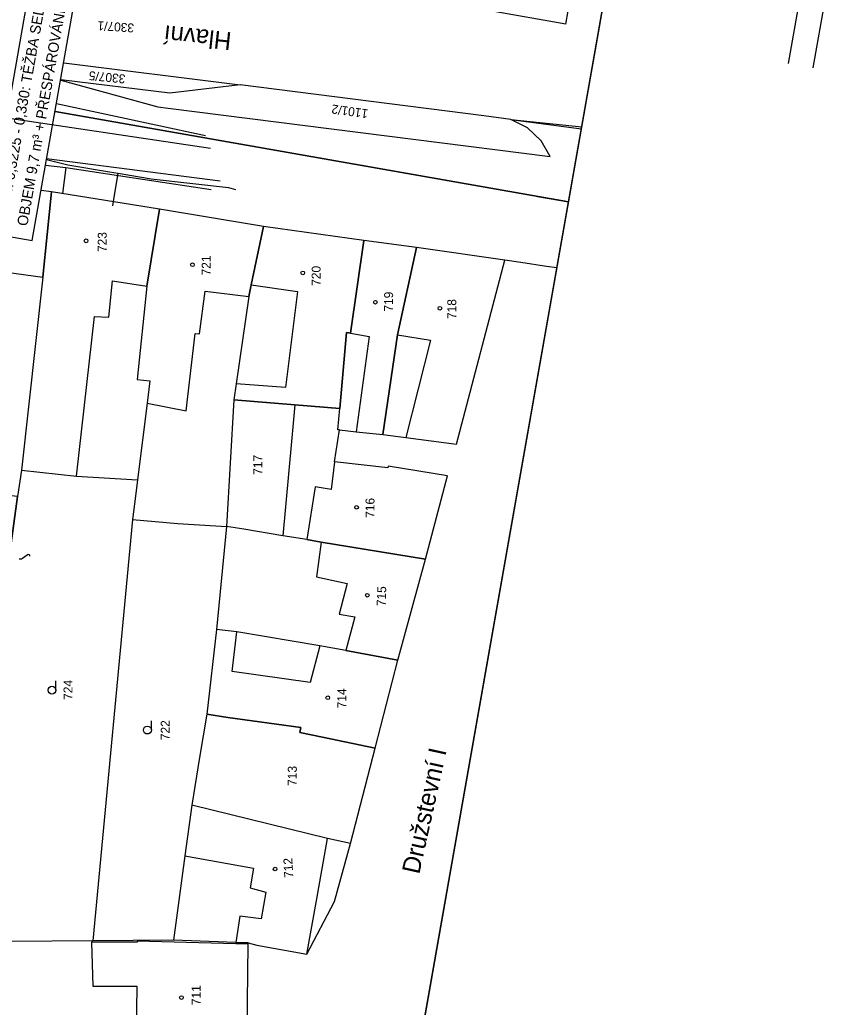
# Model space of a CAD drawing. Extents: x -534481 to -534256, y -1190577 to -1190138.
# Drawn here: x -534332 to -534255.5, y -1190343.4 to -1190249.6 of the extents above; entities that cross this region are included whole.
import ezdxf

# ---------------------------------------------------------------- set-up
doc = ezdxf.new("R2010")
doc.units = 0
for name, color, linetype in [('07_KANALIZACE', 7, 'Continuous'), ('14', 7, 'Continuous'), ('30', 7, 'Continuous'), ('31', 7, 'Continuous'), ('_N_text', 7, 'Continuous'), ('_rozpiska', 7, 'Continuous'), ('_rámeček', 7, 'Continuous'), ('_rámeček_mřížka', 7, 'Continuous'), ('_tenka', 7, 'Continuous'), ('Hranice parcel', 7, 'Continuous'), ('Parcelní čísla', 7, 'Continuous'), ('Polygon budovy', 7, 'Continuous'), ('Pop  PČ popisy', 7, 'Continuous'), ('Vrstva 1', 7, 'Continuous'), ('Značky budov', 7, 'Continuous'), ('Značky kultur', 7, 'Continuous')]:
    doc.layers.add(name, color=color, linetype=linetype)

msp = doc.modelspace()

# ---------------------------------------------------------------- linework, layer by layer
at = {"layer": '07_KANALIZACE'}
msp.add_line((-534328.555, -1190257.533), (-534314.388, -1190260.556), dxfattribs=at)
at = {"layer": '14'}
for points in [[(-534329.584, -1190263.371), (-534327.65, -1190263.6), (-534320.14, -1190264.75), (-534313.856, -1190265.686)], [(-534327.65, -1190263.6), (-534327.96, -1190266.08)]]:
    msp.add_lwpolyline(points, dxfattribs=at)
at = {"layer": '30'}
msp.add_line((-534258.995, -1190253.718), (-534257.831, -1190247.114), dxfattribs=at)
msp.add_lwpolyline([(-534332.097, -1190300.767), (-534331.981, -1190300.776), (-534331.867, -1190300.751), (-534331.755, -1190300.692), (-534331.313, -1190300.387), (-534331.218, -1190300.337), (-534331.152, -1190300.34), (-534331.115, -1190300.395), (-534331.109, -1190300.503)], dxfattribs=at)
at = {"layer": '31'}
msp.add_line((-534255.512, -1190247.523), (-534256.676, -1190254.127), dxfattribs=at)
at = {"layer": '_N_text'}
msp.add_lwpolyline([(-534329.865, -1190239.303), (-534335.236, -1190269.762), (-534330.848, -1190270.536), (-534325.477, -1190240.077)], close=True, dxfattribs=at)
at = {"layer": '_rozpiska'}
for q in [(-534265.393, -1190166.262), (-534313.394, -1190244.109)]:
    msp.add_line((-534280.153, -1190249.971), q, dxfattribs=at)
at = {"layer": '_rámeček'}
for p, q in [((-534279.901, -1190266.866), (-534261.668, -1190163.461)), ((-534298.134, -1190370.27), (-534279.901, -1190266.866))]:
    msp.add_line(p, q, dxfattribs=at)
for points in [[(-534407.912, -1190137.674), (-534480.845, -1190551.293), (-534334.601, -1190577.08), (-534261.668, -1190163.461)], [(-534328.654, -1190258.269), (-534279.901, -1190266.866)], [(-534279.901, -1190266.866), (-534328.654, -1190258.269)]]:
    msp.add_lwpolyline(points, dxfattribs=at)
at = {"layer": '_rámeček_mřížka'}
msp.add_line((-534282.856, -1190266.345), (-534279.901, -1190266.866), dxfattribs=at)
msp.add_lwpolyline([(-534480.845, -1190551.293), (-534334.601, -1190577.08), (-534261.668, -1190163.461)], dxfattribs=at)
at = {"layer": '_tenka'}
msp.add_lwpolyline([(-534367.462, -1190255.872), (-534340.907, -1190257.743), (-534313.909, -1190261.752)], dxfattribs=at)
at = {"layer": 'Hranice parcel'}
for p, q in [((-534327.842, -1190253.66), (-534311.1, -1190255.76)), ((-534318.76, -1190267.54), (-534329.03, -1190265.92)), ((-534308.86, -1190269.19), (-534318.76, -1190267.54)), ((-534299.34, -1190270.54), (-534308.86, -1190269.19)), ((-534294.34, -1190271.21), (-534299.34, -1190270.54)), ((-534285.95, -1190272.39), (-534294.34, -1190271.21)), ((-534311.69, -1190285.66), (-534312.39, -1190297.68)), ((-534305.91, -1190286.14), (-534311.69, -1190285.66)), ((-534305.91, -1190286.14), (-534306.23, -1190289.63)), ((-534301.62, -1190286.49), (-534305.91, -1190286.14)), ((-534306.23, -1190289.63), (-534307.05, -1190298.57)), ((-534321.31, -1190297.03), (-534325.09, -1190337.06)), ((-534312.39, -1190297.68), (-534313.35, -1190307.49)), ((-534296.1, -1190310.4), (-534293.5, -1190300.81)), ((-534313.35, -1190307.49), (-534314.25, -1190315.51)), ((-534298.26, -1190318.76), (-534296.1, -1190310.4)), ((-534300.61, -1190327.81), (-534298.26, -1190318.76)), ((-534325.09, -1190337.06), (-534332.83, -1190337.12)), ((-534317.41, -1190337), (-534325.09, -1190337.06))]:
    msp.add_line(p, q, dxfattribs=at)
for points in [[(-534328.129, -1190255.292), (-534318.9, -1190257.84), (-534317.93, -1190257.96), (-534281.65, -1190262.55), (-534282.51, -1190261.06), (-534283.8, -1190259.83), (-534285.39, -1190259.03)], [(-534311.1, -1190255.76), (-534317.76, -1190256.55), (-534328.125, -1190255.269)], [(-534285.39, -1190259.03), (-534287.93, -1190258.69), (-534311.1, -1190255.76)], [(-534285.39, -1190259.03), (-534278.677, -1190259.924)], [(-534285.39, -1190259.03), (-534278.645, -1190259.742)], [(-534329.03, -1190265.92), (-534330.011, -1190265.792)], [(-534329.03, -1190265.92), (-534329.83, -1190274.01), (-534331.85, -1190292.36)], [(-534318.76, -1190267.54), (-534319.95, -1190274.86), (-534320.89, -1190283.73), (-534319.66, -1190283.86), (-534319.92, -1190285.99), (-534320.83, -1190293.25)], [(-534308.86, -1190269.19), (-534310.04, -1190274.74), (-534310.28, -1190275.84), (-534311.47, -1190284.16), (-534311.69, -1190285.66)], [(-534299.34, -1190270.54), (-534300.62, -1190279.32), (-534300.98, -1190279.26), (-534301.62, -1190286.49)], [(-534294.34, -1190271.21), (-534296.16, -1190279.48), (-534297.54, -1190288.96)], [(-534297.54, -1190288.96), (-534295.37, -1190289.25), (-534290.54, -1190289.89), (-534285.95, -1190272.39)], [(-534281.008, -1190273.142), (-534282, -1190272.99), (-534284.44, -1190272.62), (-534285.95, -1190272.39)], [(-534301.66, -1190288.52), (-534301.8, -1190288.5), (-534301.62, -1190286.49)], [(-534293.5, -1190300.81), (-534291.39, -1190292.89), (-534297.04, -1190291.98), (-534297.07, -1190292.12), (-534302.14, -1190291.55), (-534301.66, -1190288.52)], [(-534301.66, -1190288.52), (-534300.07, -1190288.69), (-534297.54, -1190288.96)], [(-534331.85, -1190292.36), (-534332.25, -1190294.85), (-534333.12, -1190301.37), (-534333.95, -1190307.91)], [(-534331.85, -1190292.36), (-534326.64, -1190292.92), (-534320.83, -1190293.25)], [(-534320.83, -1190293.25), (-534320.97, -1190294.31), (-534321.31, -1190297.03)], [(-534321.31, -1190297.03), (-534317.01, -1190297.41), (-534312.39, -1190297.68)], [(-534307.05, -1190298.57), (-534310.73, -1190297.96), (-534312.39, -1190297.68)], [(-534293.5, -1190300.81), (-534303.4, -1190299.17), (-534304.76, -1190298.94), (-534307.05, -1190298.57)], [(-534296.1, -1190310.4), (-534301.05, -1190309.46), (-534303.52, -1190309.04), (-534311.4, -1190307.7), (-534313.35, -1190307.49)], [(-534314.25, -1190315.51), (-534314.94, -1190319.65), (-534315.69, -1190324.17)], [(-534298.26, -1190318.76), (-534303.28, -1190317.7), (-534305.42, -1190317.25), (-534305.33, -1190316.8), (-534312.25, -1190315.85), (-534314.25, -1190315.51)], [(-534315.69, -1190324.17), (-534316.34, -1190328.99), (-534317.41, -1190337)], [(-534300.61, -1190327.81), (-534302.8, -1190327.32), (-534315.69, -1190324.17)], [(-534310.32, -1190337.25), (-534309.51, -1190337.45), (-534304.75, -1190338.32), (-534302.13, -1190333.32), (-534300.61, -1190327.81)], [(-534310.32, -1190337.25), (-534311.5, -1190337.21), (-534317.41, -1190337)], [(-534315.73, -1190352.48), (-534310.81, -1190348.3), (-534310.45, -1190348.3), (-534310.32, -1190337.38), (-534310.32, -1190337.25)]]:
    msp.add_lwpolyline(points, dxfattribs=at)
at = {"layer": 'Polygon budovy'}
msp.add_lwpolyline([(-534334.434, -1190265.214), (-534341.12, -1190264.34), (-534341.18, -1190264.8), (-534342.09, -1190272.42), (-534339.77, -1190272.69), (-534343.2, -1190300.17), (-534333.12, -1190301.37), (-534332.25, -1190294.85), (-534337.72, -1190294.22), (-534334.94, -1190273.31), (-534329.83, -1190274.01), (-534329.03, -1190265.92), (-534330.011, -1190265.792)], dxfattribs=at)
for points in [[(-534329.03, -1190265.92), (-534329.83, -1190274.01), (-534331.85, -1190292.36), (-534326.64, -1190292.92), (-534324.94, -1190277.76), (-534323.57, -1190277.82), (-534323.23, -1190274.35), (-534319.95, -1190274.86), (-534318.76, -1190267.54)], [(-534319.92, -1190285.99), (-534316.22, -1190286.71), (-534315.36, -1190279.35), (-534314.97, -1190279.41), (-534314.43, -1190275.35), (-534310.28, -1190275.84), (-534310.04, -1190274.74), (-534308.86, -1190269.19), (-534318.76, -1190267.54), (-534319.95, -1190274.86), (-534320.89, -1190283.73), (-534319.66, -1190283.86)], [(-534311.69, -1190285.66), (-534305.91, -1190286.14), (-534301.62, -1190286.49), (-534300.98, -1190279.26), (-534300.62, -1190279.32), (-534299.34, -1190270.54), (-534308.86, -1190269.19), (-534310.04, -1190274.74), (-534305.65, -1190275.36), (-534306.77, -1190284.49), (-534311.47, -1190284.16)], [(-534300.07, -1190288.69), (-534297.54, -1190288.96), (-534296.16, -1190279.48), (-534294.34, -1190271.21), (-534299.34, -1190270.54), (-534300.62, -1190279.32), (-534298.85, -1190279.64)], [(-534295.37, -1190289.25), (-534290.54, -1190289.89), (-534285.95, -1190272.39), (-534294.34, -1190271.21), (-534296.16, -1190279.48), (-534293, -1190280.01)], [(-534302.14, -1190291.55), (-534302.44, -1190294.18), (-534303.96, -1190293.94), (-534304.76, -1190298.94), (-534303.4, -1190299.17), (-534293.5, -1190300.81), (-534291.39, -1190292.89), (-534297.04, -1190291.98), (-534297.07, -1190292.12)], [(-534301.7, -1190306.03), (-534300.21, -1190306.28), (-534301.05, -1190309.46), (-534296.1, -1190310.4), (-534293.5, -1190300.81), (-534303.4, -1190299.17), (-534303.85, -1190302.47), (-534300.92, -1190303.1)], [(-534314.25, -1190315.51), (-534312.25, -1190315.85), (-534305.33, -1190316.8), (-534305.42, -1190317.25), (-534303.28, -1190317.7), (-534298.26, -1190318.76), (-534296.1, -1190310.4), (-534301.05, -1190309.46), (-534303.52, -1190309.04), (-534304.43, -1190312.52), (-534311.84, -1190311.46), (-534311.4, -1190307.7), (-534313.35, -1190307.49)], [(-534310.13, -1190332), (-534308.64, -1190332.42), (-534309.09, -1190334.97), (-534311.12, -1190334.7), (-534311.5, -1190337.21), (-534310.32, -1190337.25), (-534309.51, -1190337.45), (-534304.75, -1190338.32), (-534303.82, -1190333.06), (-534302.8, -1190327.32), (-534315.69, -1190324.17), (-534316.34, -1190328.99), (-534309.81, -1190330.15)], [(-534320.89, -1190337.07), (-534320.88, -1190337.18), (-534325.2, -1190337.17), (-534325.09, -1190341.34), (-534320.9, -1190341.35), (-534320.99, -1190348.17), (-534318.18, -1190348.21), (-534317.67, -1190349.12), (-534315.85, -1190349.15), (-534315.3, -1190348.25), (-534310.81, -1190348.3), (-534310.45, -1190348.3), (-534310.32, -1190337.38)]]:
    msp.add_lwpolyline(points, close=True, dxfattribs=at)
at = {"layer": 'Vrstva 1'}
for points in [[(-534329.491, -1190262.84), (-534327.45, -1190263.33)], [(-534329.491, -1190262.84), (-534327.45, -1190263.33), (-534323.495, -1190263.995), (-534322.692, -1190264.13)], [(-534312.982, -1190264.901), (-534329.478, -1190262.769)], [(-534323.185, -1190267.23), (-534323.122, -1190266.835), (-534322.692, -1190264.13)], [(-534322.692, -1190264.13), (-534319.54, -1190264.66), (-534312.19, -1190265.5), (-534311.55, -1190265.69)]]:
    msp.add_lwpolyline(points, dxfattribs=at)
at = {"layer": 'Značky budov'}
for centre in [(-534325.734, -1190270.561), (-534315.624, -1190272.83), (-534305.15, -1190273.607), (-534298.249, -1190276.391), (-534292.112, -1190276.961), (-534300.031, -1190295.875), (-534299.013, -1190304.229), (-534302.768, -1190313.963), (-534307.779, -1190330.228), (-534316.673, -1190342.442)]:
    msp.add_circle(centre, 0.175, dxfattribs=at)
at = {"layer": 'Značky kultur'}
for p, q in [((-534328.593, -1190313.24), (-534328.593, -1190312.365)), ((-534319.53, -1190317.029), (-534319.53, -1190316.154))]:
    msp.add_line(p, q, dxfattribs=at)
for centre in [(-534328.968, -1190313.24), (-534319.905, -1190317.028)]:
    msp.add_circle(centre, 0.375, dxfattribs=at)

# ---------------------------------------------------------------- texts
at = {"layer": '_N_text'}
for s, p in [('Ř. KM 0,3225 - 0,330: TĚŽBA SEDIMENTU ', (-534333.264, -1190268.867)), ('OBJEM 9,7 m³ + PŘESPÁROVÁNÍ DLAŽBY', (-534331.31, -1190269.211))]:
    msp.add_text(s, height=1, rotation=80.02054, dxfattribs=at).set_placement(p)
at = {"layer": 'Parcelní čísla'}
for s, rotation, p in [('3307/1', 176, (-534321.145, -1190249.934)), ('3307/5', 174.33625, (-534321.96, -1190254.777)), ('1101/2', 172, (-534298.895, -1190258.092)), ('723', 90, (-534323.771, -1190271.628)), ('721', 90, (-534313.896, -1190273.849)), ('720', 90, (-534303.453, -1190274.834)), ('719', 90, (-534296.563, -1190277.287)), ('718', 90, (-534290.564, -1190277.989)), ('717', 90, (-534308.988, -1190292.79)), ('716', 90, (-534298.332, -1190296.875)), ('715', 88, (-534297.278, -1190305.279)), ('724', 90, (-534327.02, -1190314.164)), ('714', 90, (-534301.017, -1190314.963)), ('722', 90, (-534317.781, -1190317.992)), ('713', 90, (-534305.714, -1190322.333)), ('712', 93, (-534306.044, -1190331.048)), ('711', 90, (-534314.841, -1190343.164))]:
    msp.add_text(s, height=0.85, rotation=rotation, dxfattribs=at).set_placement(p)
at = {"layer": 'Pop  PČ popisy'}
for s, rotation, p in [('Hlavní', 173.78778, (-534311.849, -1190250.771)), ('Družstevní I', 77.51557, (-534294.084, -1190330.787))]:
    msp.add_text(s, height=1.7, rotation=rotation, dxfattribs=at).set_placement(p)

doc.saveas('drawing.dxf')
